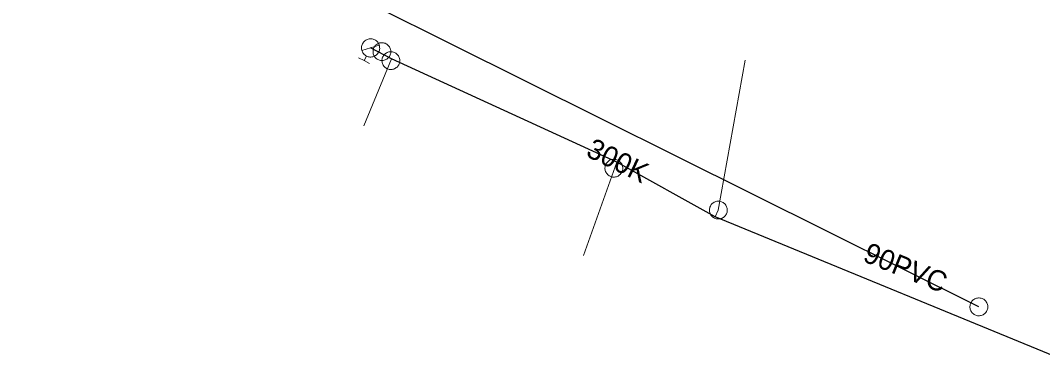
# Model space of a CAD drawing. Extents: x -741806 to -738704, y -1059275 to -1055387.
# Drawn here: x -740211.6 to -740161.4, y -1056739.6 to -1056722.4 of the extents above; entities that cross this region are included whole.
import ezdxf

# ---------------------------------------------------------------- set-up
doc = ezdxf.new("R2010")
doc.units = 0
doc.header["$LTSCALE"] = 0.4
for name, color, linetype, lineweight in [('2', 7, 'Continuous', 25), ('21', 7, 'Continuous', 13), ('3', 7, 'Continuous', 13), ('50', 7, 'Continuous', 13), ('51', 7, 'Continuous', 13), ('52', 7, 'Continuous', 25)]:
    doc.layers.add(name, color=color, linetype=linetype, lineweight=lineweight)
doc.layers.add('5', color=7, linetype='Continuous')
doc.layers.add('53', color=7, linetype='Continuous')

msp = doc.modelspace()

# ---------------------------------------------------------------- linework, layer by layer
at = {"layer": '2'}
msp.add_lwpolyline([(-740164.57, -1056736.46), (-740197.87, -1056719.87), (-740211.579, -1056705.889)], dxfattribs=at)
at = {"layer": '21'}
for p, q in [((-740193.381, -1056724.299), (-740194.73, -1056727.587)), ((-740182.329, -1056729.371), (-740183.954, -1056733.938))]:
    msp.add_line(p, q, dxfattribs=at)
msp.add_lwpolyline([(-740177.508, -1056732.041), (-740177.349, -1056731.715), (-740176.026, -1056724.369)], dxfattribs=at)
at = {"layer": '3'}
msp.add_lwpolyline([(-740164.961, -1056736.264), (-740164.979, -1056736.305), (-740164.993, -1056736.349), (-740165.002, -1056736.394), (-740165.006, -1056736.439), (-740165.006, -1056736.485), (-740165.001, -1056736.531), (-740164.99, -1056736.575), (-740164.976, -1056736.619), (-740164.957, -1056736.66), (-740164.934, -1056736.7), (-740164.907, -1056736.737), (-740164.876, -1056736.771), (-740164.841, -1056736.801), (-740164.804, -1056736.828), (-740164.764, -1056736.85), (-740164.722, -1056736.869), (-740164.678, -1056736.882), (-740164.634, -1056736.892), (-740164.588, -1056736.896), (-740164.542, -1056736.895), (-740164.497, -1056736.89), (-740164.453, -1056736.88), (-740164.409, -1056736.865), (-740164.367, -1056736.847), (-740164.327, -1056736.823), (-740164.291, -1056736.795), (-740164.257, -1056736.765), (-740164.226, -1056736.73), (-740164.2, -1056736.693), (-740164.178, -1056736.653), (-740164.159, -1056736.612), (-740164.146, -1056736.568), (-740164.136, -1056736.523), (-740164.132, -1056736.477), (-740164.132, -1056736.432), (-740164.137, -1056736.386), (-740164.148, -1056736.342), (-740164.163, -1056736.297), (-740164.181, -1056736.257), (-740164.204, -1056736.217), (-740164.232, -1056736.18), (-740164.262, -1056736.146), (-740164.297, -1056736.116), (-740164.334, -1056736.089), (-740164.374, -1056736.067), (-740164.416, -1056736.048), (-740164.459, -1056736.034), (-740164.504, -1056736.026), (-740164.55, -1056736.022), (-740164.596, -1056736.022), (-740164.641, -1056736.028), (-740164.686, -1056736.037), (-740164.73, -1056736.052), (-740164.771, -1056736.07), (-740164.811, -1056736.094), (-740164.848, -1056736.121), (-740164.881, -1056736.152), (-740164.912, -1056736.187), (-740164.938, -1056736.224), (-740164.961, -1056736.263)], dxfattribs=at)
at = {"layer": '50'}
for p, q in [((-740194.407, -1056723.765), (-740193.981, -1056723.629)), ((-740194.407, -1056723.765), (-740194.83, -1056723.899)), ((-740194.611, -1056724.163), (-740194.726, -1056724.387)), ((-740194.999, -1056724.246), (-740194.726, -1056724.387)), ((-740194.452, -1056724.528), (-740194.726, -1056724.387))]:
    msp.add_line(p, q, dxfattribs=at)
msp.add_lwpolyline([(-740194.8, -1056723.559), (-740194.82, -1056723.604), (-740194.837, -1056723.647), (-740194.846, -1056723.694), (-740194.851, -1056723.74), (-740194.852, -1056723.784), (-740194.847, -1056723.833), (-740194.837, -1056723.877), (-740194.824, -1056723.924), (-740194.806, -1056723.966), (-740194.782, -1056724.006), (-740194.755, -1056724.044), (-740194.726, -1056724.081), (-740194.689, -1056724.111), (-740194.652, -1056724.139), (-740194.613, -1056724.163), (-740194.57, -1056724.181), (-740194.528, -1056724.197), (-740194.481, -1056724.207), (-740194.434, -1056724.212), (-740194.387, -1056724.213), (-740194.341, -1056724.208), (-740194.295, -1056724.199), (-740194.251, -1056724.185), (-740194.209, -1056724.167), (-740194.167, -1056724.143), (-740194.128, -1056724.117), (-740194.094, -1056724.086), (-740194.061, -1056724.052), (-740194.035, -1056724.013), (-740194.009, -1056723.975), (-740193.99, -1056723.931), (-740193.976, -1056723.886), (-740193.966, -1056723.843), (-740193.959, -1056723.795), (-740193.96, -1056723.748), (-740193.963, -1056723.702), (-740193.974, -1056723.657), (-740193.986, -1056723.611), (-740194.006, -1056723.567), (-740194.029, -1056723.528), (-740194.057, -1056723.489), (-740194.088, -1056723.455), (-740194.12, -1056723.423), (-740194.16, -1056723.393), (-740194.2, -1056723.37), (-740194.242, -1056723.351), (-740194.286, -1056723.338), (-740194.332, -1056723.326), (-740194.378, -1056723.321), (-740194.426, -1056723.321), (-740194.471, -1056723.325), (-740194.518, -1056723.334), (-740194.562, -1056723.348), (-740194.604, -1056723.365), (-740194.644, -1056723.391), (-740194.684, -1056723.415), (-740194.719, -1056723.447), (-740194.749, -1056723.482), (-740194.777, -1056723.519)], close=True, dxfattribs=at)
at = {"layer": '51'}
for points in [[(-740194.238, -1056723.749), (-740194.257, -1056723.79), (-740194.271, -1056723.833), (-740194.281, -1056723.879), (-740194.286, -1056723.924), (-740194.286, -1056723.97), (-740194.282, -1056724.016), (-740194.272, -1056724.06), (-740194.258, -1056724.104), (-740194.239, -1056724.145), (-740194.217, -1056724.185), (-740194.19, -1056724.223), (-740194.16, -1056724.257), (-740194.126, -1056724.288), (-740194.089, -1056724.315), (-740194.049, -1056724.338), (-740194.007, -1056724.357), (-740193.964, -1056724.371), (-740193.919, -1056724.381), (-740193.873, -1056724.385), (-740193.827, -1056724.385), (-740193.782, -1056724.381), (-740193.737, -1056724.372), (-740193.694, -1056724.357), (-740193.652, -1056724.339), (-740193.612, -1056724.316), (-740193.574, -1056724.289), (-740193.541, -1056724.259), (-740193.51, -1056724.225), (-740193.483, -1056724.188), (-740193.459, -1056724.148), (-740193.441, -1056724.107), (-740193.427, -1056724.064), (-740193.417, -1056724.018), (-740193.412, -1056723.974), (-740193.412, -1056723.928), (-740193.416, -1056723.881), (-740193.426, -1056723.837), (-740193.44, -1056723.793), (-740193.459, -1056723.752), (-740193.481, -1056723.712), (-740193.508, -1056723.675), (-740193.539, -1056723.64), (-740193.573, -1056723.61), (-740193.609, -1056723.582), (-740193.649, -1056723.56), (-740193.691, -1056723.54), (-740193.735, -1056723.527), (-740193.779, -1056723.516), (-740193.825, -1056723.512), (-740193.871, -1056723.512), (-740193.916, -1056723.517), (-740193.961, -1056723.525), (-740194.004, -1056723.54), (-740194.046, -1056723.558), (-740194.086, -1056723.581), (-740194.124, -1056723.608), (-740194.157, -1056723.638), (-740194.188, -1056723.672), (-740194.215, -1056723.709), (-740194.237, -1056723.748)], [(-740193.576, -1056724.793), (-740193.534, -1056724.808), (-740193.489, -1056724.818), (-740193.443, -1056724.824), (-740193.398, -1056724.826), (-740193.352, -1056724.822), (-740193.307, -1056724.813), (-740193.263, -1056724.8), (-740193.221, -1056724.783), (-740193.181, -1056724.76), (-740193.143, -1056724.734), (-740193.108, -1056724.705), (-740193.076, -1056724.671), (-740193.049, -1056724.635), (-740193.025, -1056724.596), (-740193.006, -1056724.554), (-740192.99, -1056724.511), (-740192.979, -1056724.467), (-740192.974, -1056724.421), (-740192.973, -1056724.375), (-740192.977, -1056724.329), (-740192.986, -1056724.285), (-740192.998, -1056724.241), (-740193.016, -1056724.199), (-740193.038, -1056724.158), (-740193.064, -1056724.121), (-740193.094, -1056724.086), (-740193.127, -1056724.055), (-740193.164, -1056724.027), (-740193.203, -1056724.003), (-740193.245, -1056723.983), (-740193.287, -1056723.968), (-740193.332, -1056723.958), (-740193.378, -1056723.952), (-740193.423, -1056723.951), (-740193.469, -1056723.955), (-740193.514, -1056723.963), (-740193.558, -1056723.976), (-740193.6, -1056723.993), (-740193.64, -1056724.016), (-740193.677, -1056724.042), (-740193.712, -1056724.072), (-740193.744, -1056724.105), (-740193.771, -1056724.142), (-740193.796, -1056724.18), (-740193.815, -1056724.222), (-740193.831, -1056724.265), (-740193.84, -1056724.31), (-740193.847, -1056724.355), (-740193.848, -1056724.401), (-740193.844, -1056724.447), (-740193.835, -1056724.492), (-740193.823, -1056724.536), (-740193.804, -1056724.578), (-740193.783, -1056724.618), (-740193.757, -1056724.656), (-740193.727, -1056724.691), (-740193.694, -1056724.721), (-740193.657, -1056724.75), (-740193.618, -1056724.773), (-740193.577, -1056724.792)], [(-740182.619, -1056730.073), (-740182.576, -1056730.086), (-740182.532, -1056730.095), (-740182.485, -1056730.099), (-740182.44, -1056730.098), (-740182.395, -1056730.091), (-740182.35, -1056730.081), (-740182.307, -1056730.065), (-740182.265, -1056730.046), (-740182.227, -1056730.022), (-740182.19, -1056729.994), (-740182.157, -1056729.963), (-740182.126, -1056729.928), (-740182.1, -1056729.891), (-740182.079, -1056729.85), (-740182.061, -1056729.808), (-740182.048, -1056729.764), (-740182.039, -1056729.719), (-740182.036, -1056729.674), (-740182.037, -1056729.627), (-740182.043, -1056729.582), (-740182.054, -1056729.538), (-740182.069, -1056729.494), (-740182.089, -1056729.453), (-740182.112, -1056729.414), (-740182.141, -1056729.377), (-740182.172, -1056729.344), (-740182.206, -1056729.315), (-740182.245, -1056729.288), (-740182.285, -1056729.267), (-740182.327, -1056729.248), (-740182.37, -1056729.236), (-740182.415, -1056729.228), (-740182.462, -1056729.224), (-740182.507, -1056729.225), (-740182.552, -1056729.231), (-740182.597, -1056729.241), (-740182.64, -1056729.257), (-740182.682, -1056729.276), (-740182.72, -1056729.301), (-740182.757, -1056729.328), (-740182.79, -1056729.36), (-740182.821, -1056729.394), (-740182.846, -1056729.432), (-740182.868, -1056729.472), (-740182.886, -1056729.515), (-740182.899, -1056729.559), (-740182.907, -1056729.604), (-740182.911, -1056729.649), (-740182.909, -1056729.695), (-740182.903, -1056729.741), (-740182.893, -1056729.785), (-740182.878, -1056729.828), (-740182.858, -1056729.869), (-740182.835, -1056729.908), (-740182.806, -1056729.945), (-740182.775, -1056729.979), (-740182.741, -1056730.008), (-740182.702, -1056730.034), (-740182.662, -1056730.056), (-740182.62, -1056730.073)], [(-740177.157, -1056731.322), (-740177.198, -1056731.304), (-740177.242, -1056731.29), (-740177.288, -1056731.282), (-740177.332, -1056731.278), (-740177.378, -1056731.279), (-740177.424, -1056731.284), (-740177.469, -1056731.295), (-740177.512, -1056731.309), (-740177.553, -1056731.329), (-740177.592, -1056731.352), (-740177.629, -1056731.38), (-740177.663, -1056731.411), (-740177.693, -1056731.446), (-740177.719, -1056731.483), (-740177.741, -1056731.524), (-740177.759, -1056731.566), (-740177.773, -1056731.609), (-740177.781, -1056731.654), (-740177.785, -1056731.7), (-740177.784, -1056731.746), (-740177.778, -1056731.791), (-740177.768, -1056731.836), (-740177.753, -1056731.879), (-740177.734, -1056731.921), (-740177.71, -1056731.96), (-740177.682, -1056731.997), (-740177.651, -1056732.03), (-740177.616, -1056732.06), (-740177.579, -1056732.086), (-740177.539, -1056732.109), (-740177.497, -1056732.126), (-740177.453, -1056732.139), (-740177.408, -1056732.148), (-740177.363, -1056732.152), (-740177.317, -1056732.151), (-740177.271, -1056732.146), (-740177.227, -1056732.135), (-740177.183, -1056732.121), (-740177.142, -1056732.101), (-740177.103, -1056732.077), (-740177.066, -1056732.05), (-740177.032, -1056732.018), (-740177.003, -1056731.984), (-740176.976, -1056731.947), (-740176.954, -1056731.906), (-740176.936, -1056731.864), (-740176.923, -1056731.82), (-740176.914, -1056731.776), (-740176.91, -1056731.73), (-740176.911, -1056731.683), (-740176.917, -1056731.638), (-740176.927, -1056731.594), (-740176.942, -1056731.551), (-740176.961, -1056731.509), (-740176.985, -1056731.47), (-740177.013, -1056731.433), (-740177.044, -1056731.4), (-740177.079, -1056731.37), (-740177.116, -1056731.344), (-740177.156, -1056731.322)]]:
    msp.add_lwpolyline(points, dxfattribs=at)
at = {"layer": '52'}
msp.add_lwpolyline([(-740159.05, -1056739.629), (-740177.508, -1056732.041), (-740182.329, -1056729.371), (-740193.381, -1056724.299), (-740194.41, -1056723.77)], dxfattribs=at)

# ---------------------------------------------------------------- texts
at = {"layer": '5'}
msp.add_text('300K', height=1, rotation=334, dxfattribs=at).set_placement((-740183.895, -1056729.049))
msp.add_text('300K', height=1, rotation=334, dxfattribs=at).set_placement((-740183.895, -1056729.049))
at = {"layer": '53'}
msp.add_text('90PVC ', height=1, rotation=338, dxfattribs=at).set_placement((-740170.311, -1056734.204))

doc.saveas('drawing.dxf')
